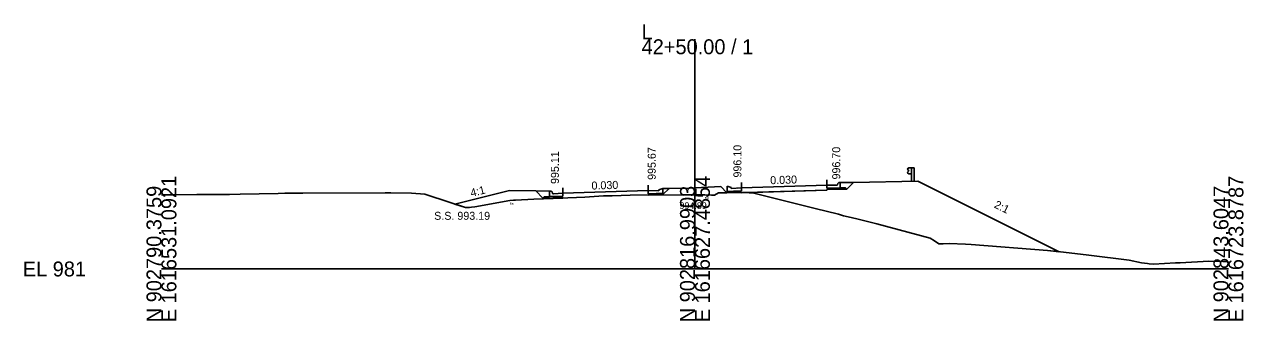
# Model space of a CAD drawing. Extents: x 1009 to 7438, y -1586 to 7964.
# Drawn here: x 4009.2 to 4237.7, y 414 to 469.6 of the extents above; entities that cross this region are included whole.
import ezdxf

# ---------------------------------------------------------------- set-up
doc = ezdxf.new("R2010")
doc.units = 0
for name, color, linetype in [('Exist Cross Section Cell', 7, 'Continuous'), ('Exist XS Center Line Elevation Label', 7, 'Continuous'), ('Exist XS Ground Line', 7, 'Continuous'), ('Prop XS Dump Level', 7, 'Continuous'), ('Prop XS Earthwork Shape', 7, 'Continuous'), ('Prop XS EOT Tick Mark', 7, 'Continuous'), ('Prop XS Finish Grade', 7, 'Continuous'), ('Prop XS Finish Grade CurbGutter', 7, 'Continuous'), ('Prop XS Finish Grade Earthwork', 7, 'Continuous'), ('Prop XS Finish Grade Pavement', 7, 'Continuous'), ('Prop XS Guardrail', 7, 'Continuous'), ('Prop XS Hydro Elevations', 7, 'Continuous'), ('Prop XS Pvmt Edge Slope', 7, 'Continuous'), ('Prop XS SE Text', 7, 'Continuous'), ('Prop XS Side Slope Text', 7, 'Continuous'), ('Prop XS SS Elevation Text', 7, 'Continuous'), ('Prop XS Subgrade CurbGutter', 7, 'Continuous'), ('Prop XS Subgrade Earthwork', 7, 'Continuous')]:
    doc.layers.add(name, color=color, linetype=linetype)

msp = doc.modelspace()

# ---------------------------------------------------------------- linework, layer by layer
at = {"layer": 'Exist Cross Section Cell'}
for p, q in [((4134.89, 423.73), (4134.89, 466.83)), ((4034.89, 423.73), (4134.89, 423.73)), ((4134.89, 423.73), (4234.89, 423.73))]:
    msp.add_line(p, q, dxfattribs=at)
at = {"layer": 'Exist XS Ground Line'}
for p, q in [((4034.89, 437.66), (4037.29, 437.67)), ((4037.29, 437.67), (4041.51, 437.69)), ((4041.51, 437.69), (4047.67, 437.72)), ((4047.67, 437.72), (4049.64, 437.75)), ((4049.64, 437.75), (4056.77, 437.91)), ((4056.77, 437.91), (4058.04, 437.93)), ((4058.04, 437.93), (4061.38, 437.95)), ((4061.38, 437.95), (4076.85, 438.02)), ((4076.85, 438.02), (4077.9, 438.01)), ((4077.9, 438.01), (4081.74, 437.97)), ((4081.74, 437.97), (4084.24, 437.76)), ((4084.24, 437.76), (4084.81, 437.57)), ((4084.81, 437.57), (4091.89, 435.28)), ((4093.63, 435.41), (4100.2, 436.55)), ((4100.2, 436.55), (4100.9, 436.62)), ((4100.9, 436.62), (4101.26, 436.65)), ((4101.26, 436.65), (4104.68, 436.8)), ((4104.68, 436.8), (4112.67, 437.12)), ((4112.67, 437.12), (4114.23, 437.21)), ((4114.23, 437.21), (4117.78, 437.43)), ((4117.78, 437.43), (4119.38, 437.48)), ((4119.38, 437.48), (4122.74, 437.57)), ((4122.74, 437.57), (4132.28, 437.63)), ((4132.28, 437.63), (4134.89, 437.62)), ((4134.89, 437.62), (4136.74, 437.62)), ((4136.74, 437.62), (4137.98, 437.57)), ((4137.98, 437.57), (4138.54, 437.56)), ((4138.54, 437.56), (4139.3, 438.02)), ((4139.3, 438.02), (4141.95, 438.08)), ((4141.95, 438.08), (4144.15, 438.1)), ((4144.15, 438.1), (4145.03, 438.02)), ((4145.03, 438.02), (4145.92, 437.93)), ((4145.92, 437.93), (4157.43, 435.07)), ((4091.89, 435.28), (4092.64, 435.28)), ((4092.64, 435.28), (4093, 435.33)), ((4093, 435.33), (4093.63, 435.41)), ((4157.43, 435.07), (4161.77, 434.01)), ((4161.77, 434.01), (4162.75, 433.72)), ((4162.75, 433.72), (4163.62, 433.5)), ((4163.62, 433.5), (4165.23, 433.15)), ((4165.23, 433.15), (4169.01, 432.2)), ((4169.01, 432.2), (4179, 429.54)), ((4179, 429.54), (4179.82, 429.04)), ((4179.82, 429.04), (4180.61, 428.46)), ((4180.61, 428.46), (4181.06, 428.46)), ((4181.06, 428.46), (4181.39, 428.45)), ((4181.39, 428.45), (4182.52, 428.52)), ((4182.52, 428.52), (4185.63, 428.4)), ((4185.63, 428.4), (4186.69, 428.3)), ((4186.69, 428.3), (4201, 427.21)), ((4201, 427.21), (4202.93, 426.98)), ((4202.93, 426.98), (4208.75, 426.33)), ((4208.75, 426.33), (4216.26, 425.36)), ((4216.26, 425.36), (4218.58, 424.88)), ((4225.86, 424.91), (4231.24, 425.17)), ((4231.24, 425.17), (4233.82, 425.16)), ((4233.82, 425.16), (4234.89, 425.08)), ((4218.58, 424.88), (4219.71, 424.75)), ((4219.71, 424.75), (4220.03, 424.7)), ((4220.03, 424.7), (4220.86, 424.66)), ((4220.86, 424.66), (4224.97, 424.88)), ((4224.97, 424.88), (4225.86, 424.91))]:
    msp.add_line(p, q, dxfattribs=at)
at = {"layer": 'Prop XS Dump Level'}
for p, q in [((4143.64, 438.97), (4159.64, 439.45)), ((4143.64, 438.97), (4159.64, 439.45)), ((4110.14, 437.96), (4126.14, 438.44)), ((4110.14, 437.96), (4126.14, 438.44))]:
    msp.add_line(p, q, dxfattribs=at)
at = {"layer": 'Prop XS Earthwork Shape'}
for points in [[(4126.14, 437.61), (4128.89, 437.69), (4130.04, 438.84), (4130.12, 438.85), (4133.76, 438.92), (4139.74, 439.19), (4140.88, 438.05), (4139.3, 438.02), (4138.54, 437.56), (4137.98, 437.57), (4136.74, 437.62), (4134.89, 437.62), (4132.28, 437.63), (4126.14, 437.59)], [(4169.01, 432.2), (4179, 429.54), (4179.82, 429.04), (4180.61, 428.46), (4181.06, 428.46), (4181.39, 428.45), (4182.52, 428.52), (4185.63, 428.4), (4186.69, 428.3), (4201, 427.21), (4203.18, 426.96), (4176.64, 440.23), (4164.64, 439.98), (4163.39, 438.73), (4159.64, 438.62), (4159.64, 438.53), (4144.44, 438.07), (4145.03, 438.02), (4145.92, 437.93), (4157.43, 435.07), (4161.77, 434.01), (4162.75, 433.72), (4163.62, 433.5), (4165.23, 433.15)], [(4104.68, 436.8), (4110.14, 437.02), (4110.14, 437.04), (4110.14, 437.13), (4106.39, 437.02), (4105.04, 438.38), (4100.14, 438.48), (4089.91, 435.92), (4091.89, 435.28), (4092.64, 435.28), (4093, 435.33), (4093.63, 435.41), (4100.2, 436.55), (4100.9, 436.62), (4101.26, 436.65)], [(4143.64, 438.09), (4143.64, 438.14), (4140.88, 438.05), (4141.95, 438.08)], [(4143.64, 438.09), (4144.15, 438.1), (4144.44, 438.07), (4143.64, 438.05)]]:
    msp.add_lwpolyline(points, close=True, dxfattribs=at)
at = {"layer": 'Prop XS EOT Tick Mark'}
for p, q in [((4110.14, 437.96), (4110.14, 438.96)), ((4126.14, 438.44), (4126.14, 439.44)), ((4143.64, 438.97), (4143.64, 439.97)), ((4159.64, 439.45), (4159.64, 440.45))]:
    msp.add_line(p, q, dxfattribs=at)
at = {"layer": 'Prop XS Finish Grade'}
for p, q in [((4128.89, 438.82), (4130.12, 438.85)), ((4162.14, 439.93), (4164.64, 439.98)), ((4107.64, 438.32), (4105.04, 438.38))]:
    msp.add_line(p, q, dxfattribs=at)
at = {"layer": 'Prop XS Finish Grade CurbGutter'}
for p, q in [((4128.14, 438.57), (4128.89, 438.82)), ((4141.65, 439), (4140.9, 439.25)), ((4141.65, 438.83), (4141.65, 439)), ((4143.64, 438.97), (4141.65, 438.83)), ((4143.64, 438.97), (4142.89, 438.91)), ((4159.64, 439.45), (4161.39, 439.43)), ((4161.39, 439.43), (4161.52, 439.45)), ((4161.52, 439.45), (4161.61, 439.54)), ((4161.61, 439.54), (4161.68, 439.79)), ((4161.68, 439.79), (4161.77, 439.88)), ((4161.89, 439.93), (4161.77, 439.88)), ((4162.14, 439.93), (4161.89, 439.93)), ((4107.64, 438.32), (4107.89, 438.32)), ((4107.89, 438.32), (4108.02, 438.29)), ((4108.11, 438.2), (4108.02, 438.29)), ((4108.18, 437.95), (4108.11, 438.2)), ((4108.27, 437.86), (4108.18, 437.95)), ((4108.39, 437.84), (4108.27, 437.86)), ((4110.14, 437.96), (4108.39, 437.84)), ((4126.14, 438.44), (4128.14, 438.4)), ((4128.14, 438.4), (4128.14, 438.57))]:
    msp.add_line(p, q, dxfattribs=at)
at = {"layer": 'Prop XS Finish Grade Earthwork'}
for p, q in [((4130.12, 438.85), (4133.76, 438.92)), ((4139.74, 439.19), (4133.76, 438.92)), ((4164.64, 439.98), (4176.64, 440.23)), ((4176.64, 440.23), (4203.18, 426.96)), ((4100.14, 438.48), (4089.91, 435.92)), ((4105.04, 438.38), (4100.14, 438.48))]:
    msp.add_line(p, q, dxfattribs=at)
at = {"layer": 'Prop XS Finish Grade Pavement'}
for p, q in [((4143.64, 438.97), (4159.64, 439.45)), ((4110.14, 437.96), (4126.14, 438.44))]:
    msp.add_line(p, q, dxfattribs=at)
at = {"layer": 'Prop XS Guardrail'}
for p, q in [((4174.7, 442.54), (4174.67, 442.48)), ((4174.67, 442.48), (4174.7, 442.42)), ((4174.7, 441.92), (4174.67, 441.86)), ((4174.67, 441.86), (4174.7, 441.8)), ((4174.99, 442.74), (4174.7, 442.54)), ((4174.7, 442.42), (4174.99, 442.22)), ((4174.99, 442.12), (4174.7, 441.92)), ((4174.7, 441.8), (4174.99, 441.6)), ((4175.49, 442.74), (4174.99, 442.74)), ((4174.99, 442.22), (4174.99, 442.12)), ((4174.99, 441.6), (4175.49, 441.6)), ((4175.99, 442.74), (4175.49, 442.74)), ((4175.49, 442.74), (4175.49, 440.24)), ((4175.99, 440.24), (4175.99, 442.74))]:
    msp.add_line(p, q, dxfattribs=at)
at = {"layer": 'Prop XS Pvmt Edge Slope'}
for p, q in [((4162.14, 438.94), (4163.14, 438.97)), ((4163.14, 438.97), (4163.39, 438.73)), ((4106.64, 437.28), (4106.39, 437.02)), ((4107.64, 437.31), (4106.64, 437.28)), ((4127.64, 437.89), (4128.89, 437.92)), ((4128.67, 437.91), (4128.89, 437.69)), ((4141.14, 438.31), (4140.88, 438.05)), ((4142.14, 438.34), (4140.9, 438.3))]:
    msp.add_line(p, q, dxfattribs=at)
at = {"layer": 'Prop XS Subgrade CurbGutter'}
for p, q in [((4128.89, 437.92), (4128.89, 438.82)), ((4140.9, 438.3), (4140.9, 439.25)), ((4143.64, 438.97), (4143.64, 438.39)), ((4159.64, 439.45), (4159.64, 438.87)), ((4159.64, 438.87), (4162.14, 438.94)), ((4162.14, 438.94), (4162.14, 439.93)), ((4107.64, 437.31), (4107.64, 438.32)), ((4110.14, 437.38), (4107.64, 437.31)), ((4110.14, 437.96), (4110.14, 437.38)), ((4126.14, 438.44), (4126.14, 437.86)), ((4126.14, 437.86), (4127.64, 437.89)), ((4143.64, 438.39), (4142.14, 438.34))]:
    msp.add_line(p, q, dxfattribs=at)
at = {"layer": 'Prop XS Subgrade Earthwork'}
for p, q in [((4128.89, 437.69), (4130.04, 438.84)), ((4140.88, 438.05), (4139.74, 439.19)), ((4163.39, 438.73), (4164.64, 439.98)), ((4106.39, 437.02), (4105.04, 438.38)), ((4110.14, 437.13), (4106.39, 437.02)), ((4110.14, 437.04), (4110.14, 437.13)), ((4110.14, 437.04), (4110.14, 437.02)), ((4126.14, 437.61), (4128.89, 437.69)), ((4126.14, 437.59), (4126.14, 437.61)), ((4143.64, 438.14), (4140.88, 438.05)), ((4143.64, 438.05), (4159.64, 438.53)), ((4143.64, 438.05), (4143.64, 438.14)), ((4159.64, 438.62), (4163.39, 438.73)), ((4159.64, 438.53), (4159.64, 438.62))]:
    msp.add_line(p, q, dxfattribs=at)

# ---------------------------------------------------------------- texts
at = {"layer": 'Exist Cross Section Cell'}
for s, p in [('L', (4124.89, 466.83)), ('42+50.00 / 1', (4124.89, 464.03)), ('EL 981', (4008.89, 422.33))]:
    msp.add_text(s, height=2.8, dxfattribs=at).set_placement(p)
for s, p in [('E 1616627.4854', (4137.69, 413.73)), ('N 902790.3759', (4034.89, 413.73)), ('E 1616531.0921', (4037.69, 413.73)), ('N 902816.9903', (4134.89, 413.73)), ('N 902843.6047', (4234.89, 413.73)), ('E 1616723.8787', (4237.69, 413.73))]:
    msp.add_text(s, height=2.8, rotation=90, dxfattribs=at).set_placement(p)
at = {"layer": 'Exist XS Center Line Elevation Label'}
msp.add_text('994.89', height=1.25, dxfattribs=at).set_placement((4131.99, 434.99))
at = {"layer": 'Prop XS Dump Level'}
for p in [(4136.75, 436.93), (4136.75, 436.93), (4136.75, 436.93), (4100.21, 435.87)]:
    msp.add_text('Eop', height=0.3, dxfattribs=at).set_placement(p)
at = {"layer": 'Prop XS Hydro Elevations'}
for s, p in [('995.11', (4109.39, 439.68)), ('995.67', (4127.54, 440.45)), ('996.10', (4143.6, 440.89)), ('996.70', (4162.12, 440.53))]:
    msp.add_text(s, height=1.5, rotation=90, dxfattribs=at).set_placement(p)
at = {"layer": 'Prop XS SE Text'}
for p in [(4149.02, 439.63), (4115.52, 438.62)]:
    msp.add_text('0.030', height=1.5, rotation=1.7184, dxfattribs=at).set_placement(p)
at = {"layer": 'Prop XS Side Slope Text'}
for s, rotation, p in [('4:1', 14.0362, (4093, 437.24)), ('2:1', 333.4349, (4190.84, 435.32))]:
    msp.add_text(s, height=1.5, rotation=rotation, dxfattribs=at).set_placement(p)
at = {"layer": 'Prop XS SS Elevation Text'}
msp.add_text('S.S. 993.19', height=1.5, dxfattribs=at).set_placement((4086.01, 432.96))

doc.saveas('drawing.dxf')
